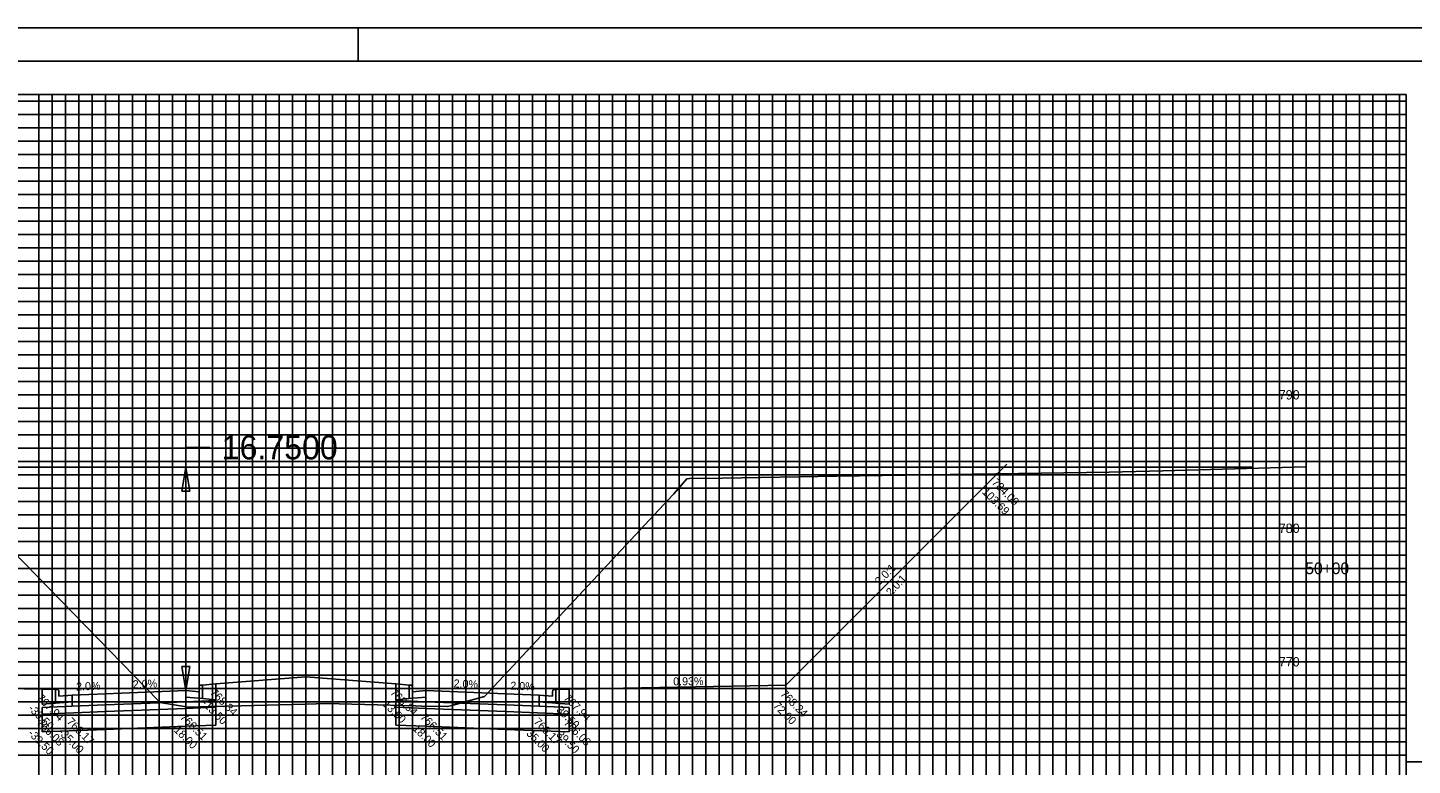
# Model space of a CAD drawing. Extents: x 578243 to 601557, y 174899 to 175559.
# Drawn here: x 600658.2 to 600865.7, y 175448.3 to 175558.8 of the extents above; entities that cross this region are included whole.
import ezdxf

# ---------------------------------------------------------------- set-up
doc = ezdxf.new("R2010")
doc.units = 0
for name, color, linetype in [('E_PROF_Grid', 7, 'Continuous'), ('E_PROF_GridMin', 7, 'Continuous'), ('P_CRDR_Label', 7, 'Continuous'), ('P_CRDR_Link', 7, 'Continuous'), ('P_E_XS_Ground', 7, 'Continuous'), ('P_RW_SlopeIntercepts', 7, 'Continuous'), ('P_XS_Text', 7, 'Continuous'), ('PLT_Sheet_Border', 7, 'Continuous'), ('PLT_Sheet_Info', 7, 'Continuous')]:
    doc.layers.add(name, color=color, linetype=linetype)

msp = doc.modelspace()

# ---------------------------------------------------------------- linework, layer by layer
at = {"layer": 'E_PROF_Grid'}
for p, q in [((600659.84, 175353.8), (600659.84, 175548.8)), ((600669.84, 175353.8), (600669.84, 175548.8)), ((600679.84, 175353.8), (600679.84, 175548.8)), ((600689.84, 175353.8), (600689.84, 175548.8)), ((600699.84, 175353.8), (600699.84, 175548.8)), ((600709.84, 175353.8), (600709.84, 175548.8)), ((600719.84, 175353.8), (600719.84, 175548.8)), ((600729.84, 175353.8), (600729.84, 175548.8)), ((600739.84, 175353.8), (600739.84, 175548.8)), ((600749.84, 175353.8), (600749.84, 175548.8)), ((600759.84, 175353.8), (600759.84, 175548.8)), ((600769.84, 175353.8), (600769.84, 175548.8)), ((600779.84, 175353.8), (600779.84, 175548.8)), ((600789.84, 175353.8), (600789.84, 175548.8)), ((600799.84, 175353.8), (600799.84, 175548.8)), ((600809.84, 175353.8), (600809.84, 175548.8)), ((600819.84, 175353.8), (600819.84, 175548.8)), ((600829.84, 175353.8), (600829.84, 175548.8)), ((600839.84, 175353.8), (600839.84, 175548.8)), ((600849.84, 175353.8), (600849.84, 175548.8)), ((600859.84, 175353.8), (600859.84, 175548.8)), ((600549.84, 175543.8), (600864.84, 175543.8)), ((600549.84, 175533.8), (600864.84, 175533.8)), ((600549.84, 175523.8), (600864.84, 175523.8)), ((600549.84, 175513.8), (600864.84, 175513.8)), ((600549.84, 175503.8), (600864.84, 175503.8)), ((600549.84, 175493.8), (600864.84, 175493.8)), ((600549.84, 175483.8), (600864.84, 175483.8)), ((600549.84, 175473.8), (600864.84, 175473.8)), ((600549.84, 175463.8), (600864.84, 175463.8)), ((600549.84, 175453.8), (600864.84, 175453.8))]:
    msp.add_line(p, q, dxfattribs=at)
at = {"layer": 'E_PROF_GridMin'}
for p, q in [((600661.84, 175353.8), (600661.84, 175548.8)), ((600663.84, 175353.8), (600663.84, 175548.8)), ((600665.84, 175353.8), (600665.84, 175548.8)), ((600667.84, 175353.8), (600667.84, 175548.8)), ((600671.84, 175353.8), (600671.84, 175548.8)), ((600673.84, 175353.8), (600673.84, 175548.8)), ((600675.84, 175353.8), (600675.84, 175548.8)), ((600677.84, 175353.8), (600677.84, 175548.8)), ((600681.84, 175353.8), (600681.84, 175548.8)), ((600683.84, 175353.8), (600683.84, 175548.8)), ((600685.84, 175353.8), (600685.84, 175548.8)), ((600687.84, 175353.8), (600687.84, 175548.8)), ((600691.84, 175353.8), (600691.84, 175548.8)), ((600693.84, 175353.8), (600693.84, 175548.8)), ((600695.84, 175353.8), (600695.84, 175548.8)), ((600697.84, 175353.8), (600697.84, 175548.8)), ((600701.84, 175353.8), (600701.84, 175548.8)), ((600703.84, 175353.8), (600703.84, 175548.8)), ((600705.84, 175353.8), (600705.84, 175548.8)), ((600707.84, 175353.8), (600707.84, 175548.8)), ((600711.84, 175353.8), (600711.84, 175548.8)), ((600713.84, 175353.8), (600713.84, 175548.8)), ((600715.84, 175353.8), (600715.84, 175548.8)), ((600717.84, 175353.8), (600717.84, 175548.8)), ((600721.84, 175353.8), (600721.84, 175548.8)), ((600723.84, 175353.8), (600723.84, 175548.8)), ((600725.84, 175353.8), (600725.84, 175548.8)), ((600727.84, 175353.8), (600727.84, 175548.8)), ((600731.84, 175353.8), (600731.84, 175548.8)), ((600733.84, 175353.8), (600733.84, 175548.8)), ((600735.84, 175353.8), (600735.84, 175548.8)), ((600737.84, 175353.8), (600737.84, 175548.8)), ((600741.84, 175353.8), (600741.84, 175548.8)), ((600743.84, 175353.8), (600743.84, 175548.8)), ((600745.84, 175353.8), (600745.84, 175548.8)), ((600747.84, 175353.8), (600747.84, 175548.8)), ((600751.84, 175353.8), (600751.84, 175548.8)), ((600753.84, 175353.8), (600753.84, 175548.8)), ((600755.84, 175353.8), (600755.84, 175548.8)), ((600757.84, 175353.8), (600757.84, 175548.8)), ((600761.84, 175353.8), (600761.84, 175548.8)), ((600763.84, 175353.8), (600763.84, 175548.8)), ((600765.84, 175353.8), (600765.84, 175548.8)), ((600767.84, 175353.8), (600767.84, 175548.8)), ((600771.84, 175353.8), (600771.84, 175548.8)), ((600773.84, 175353.8), (600773.84, 175548.8)), ((600775.84, 175353.8), (600775.84, 175548.8)), ((600777.84, 175353.8), (600777.84, 175548.8)), ((600781.84, 175353.8), (600781.84, 175548.8)), ((600783.84, 175353.8), (600783.84, 175548.8)), ((600785.84, 175353.8), (600785.84, 175548.8)), ((600787.84, 175353.8), (600787.84, 175548.8)), ((600791.84, 175353.8), (600791.84, 175548.8)), ((600793.84, 175353.8), (600793.84, 175548.8)), ((600795.84, 175353.8), (600795.84, 175548.8)), ((600797.84, 175353.8), (600797.84, 175548.8)), ((600801.84, 175353.8), (600801.84, 175548.8)), ((600803.84, 175353.8), (600803.84, 175548.8)), ((600805.84, 175353.8), (600805.84, 175548.8)), ((600807.84, 175353.8), (600807.84, 175548.8)), ((600811.84, 175353.8), (600811.84, 175548.8)), ((600813.84, 175353.8), (600813.84, 175548.8)), ((600815.84, 175353.8), (600815.84, 175548.8)), ((600817.84, 175353.8), (600817.84, 175548.8)), ((600821.84, 175353.8), (600821.84, 175548.8)), ((600823.84, 175353.8), (600823.84, 175548.8)), ((600825.84, 175353.8), (600825.84, 175548.8)), ((600827.84, 175353.8), (600827.84, 175548.8)), ((600831.84, 175353.8), (600831.84, 175548.8)), ((600833.84, 175353.8), (600833.84, 175548.8)), ((600835.84, 175353.8), (600835.84, 175548.8)), ((600837.84, 175353.8), (600837.84, 175548.8)), ((600841.84, 175353.8), (600841.84, 175548.8)), ((600843.84, 175353.8), (600843.84, 175548.8)), ((600845.84, 175353.8), (600845.84, 175548.8)), ((600847.84, 175353.8), (600847.84, 175548.8)), ((600851.84, 175353.8), (600851.84, 175548.8)), ((600853.84, 175353.8), (600853.84, 175548.8)), ((600855.84, 175353.8), (600855.84, 175548.8)), ((600857.84, 175353.8), (600857.84, 175548.8)), ((600861.84, 175353.8), (600861.84, 175548.8)), ((600863.84, 175353.8), (600863.84, 175548.8)), ((600549.84, 175547.8), (600864.84, 175547.8)), ((600549.84, 175545.8), (600864.84, 175545.8)), ((600549.84, 175541.8), (600864.84, 175541.8)), ((600549.84, 175539.8), (600864.84, 175539.8)), ((600549.84, 175537.8), (600864.84, 175537.8)), ((600549.84, 175535.8), (600864.84, 175535.8)), ((600549.84, 175531.8), (600864.84, 175531.8)), ((600549.84, 175529.8), (600864.84, 175529.8)), ((600549.84, 175527.8), (600864.84, 175527.8)), ((600549.84, 175525.8), (600864.84, 175525.8)), ((600549.84, 175521.8), (600864.84, 175521.8)), ((600549.84, 175519.8), (600864.84, 175519.8)), ((600549.84, 175517.8), (600864.84, 175517.8)), ((600549.84, 175515.8), (600864.84, 175515.8)), ((600549.84, 175511.8), (600864.84, 175511.8)), ((600549.84, 175509.8), (600864.84, 175509.8)), ((600549.84, 175507.8), (600864.84, 175507.8)), ((600549.84, 175505.8), (600864.84, 175505.8)), ((600549.84, 175501.8), (600864.84, 175501.8)), ((600549.84, 175499.8), (600864.84, 175499.8)), ((600549.84, 175497.8), (600864.84, 175497.8)), ((600549.84, 175495.8), (600864.84, 175495.8)), ((600549.84, 175491.8), (600864.84, 175491.8)), ((600549.84, 175489.8), (600864.84, 175489.8)), ((600549.84, 175487.8), (600864.84, 175487.8)), ((600549.84, 175485.8), (600864.84, 175485.8)), ((600549.84, 175481.8), (600864.84, 175481.8)), ((600549.84, 175479.8), (600864.84, 175479.8)), ((600549.84, 175477.8), (600864.84, 175477.8)), ((600549.84, 175475.8), (600864.84, 175475.8)), ((600549.84, 175471.8), (600864.84, 175471.8)), ((600549.84, 175469.8), (600864.84, 175469.8)), ((600549.84, 175467.8), (600864.84, 175467.8)), ((600549.84, 175465.8), (600864.84, 175465.8)), ((600549.84, 175461.8), (600864.84, 175461.8)), ((600549.84, 175459.8), (600864.84, 175459.8)), ((600549.84, 175457.8), (600864.84, 175457.8)), ((600549.84, 175455.8), (600864.84, 175455.8)), ((600549.84, 175451.8), (600864.84, 175451.8)), ((600549.84, 175449.8), (600864.84, 175449.8))]:
    msp.add_line(p, q, dxfattribs=at)
at = {"layer": 'P_CRDR_Link'}
msp.add_line((600804.95, 175493.4), (600771.84, 175460.28), dxfattribs=at)
for points in [[(600771.84, 175460.28), (600803.52, 175491.97)], [(600771.84, 175460.28), (600803.52, 175491.97)], [(600686.34, 175460.48), (600699.84, 175461.56)], [(600686.34, 175460.48), (600699.84, 175461.56)], [(600699.84, 175461.56), (600686.34, 175460.48)], [(600699.84, 175461.56), (600713.34, 175460.48)], [(600699.84, 175461.56), (600713.34, 175460.48)], [(600713.34, 175460.48), (600699.84, 175461.56)], [(600660.34, 175459.68), (600627.84, 175460.28)], [(600660.34, 175459.68), (600627.84, 175460.28)], [(600662.34, 175459.64), (600660.34, 175459.68)], [(600660.34, 175459.68), (600660.34, 175457.44)], [(600660.34, 175459.68), (600660.34, 175457.44)], [(600660.34, 175459.68), (600660.34, 175457.44)], [(600662.66, 175459.64), (600662.34, 175459.64)], [(600662.66, 175459.64), (600662.34, 175459.64)], [(600662.34, 175459.64), (600662.34, 175457.6)], [(600662.34, 175457.6), (600662.34, 175459.64)], [(600662.74, 175459.6), (600662.66, 175459.64)], [(600662.74, 175459.6), (600662.66, 175459.64)], [(600662.8, 175459.48), (600662.74, 175459.6)], [(600662.8, 175459.48), (600662.74, 175459.6)], [(600662.82, 175459.32), (600662.8, 175459.48)], [(600662.82, 175459.32), (600662.8, 175459.48)], [(600662.84, 175458.64), (600662.82, 175459.32)], [(600662.84, 175458.64), (600662.82, 175459.32)], [(600669.84, 175459), (600664.84, 175458.8)], [(600681.84, 175459.48), (600669.84, 175459)], [(600669.84, 175459), (600669.84, 175457.34)], [(600669.84, 175459), (600669.84, 175457.34)], [(600681.84, 175459.48), (600681.84, 175457.82)], [(600681.84, 175459.48), (600681.84, 175457.82)], [(600681.84, 175459.48), (600681.84, 175457.82)], [(600681.84, 175459.48), (600683.84, 175459.32)], [(600681.84, 175459.48), (600683.84, 175459.32)], [(600681.84, 175458.48), (600681.84, 175459.48)], [(600683.84, 175459.32), (600683.85, 175460)], [(600683.84, 175459.32), (600683.85, 175460)], [(600683.85, 175460), (600683.88, 175460.16)], [(600683.85, 175460), (600683.88, 175460.16)], [(600683.88, 175460.16), (600683.94, 175460.28)], [(600683.88, 175460.16), (600683.94, 175460.28)], [(600683.94, 175460.28), (600684.02, 175460.32)], [(600683.94, 175460.28), (600684.02, 175460.32)], [(600684.02, 175460.32), (600684.34, 175460.32)], [(600684.02, 175460.32), (600684.34, 175460.32)], [(600684.34, 175460.32), (600686.34, 175460.48)], [(600684.34, 175460.32), (600684.34, 175458.28)], [(600684.34, 175458.28), (600684.34, 175460.32)], [(600686.34, 175460.48), (600686.34, 175458.12)], [(600686.34, 175460.48), (600686.34, 175458.12)], [(600686.34, 175460.48), (600686.34, 175458.12)], [(600686.34, 175460.48), (600686.34, 175460.48)], [(600686.34, 175460.48), (600686.34, 175460.48)], [(600686.34, 175460.48), (600686.34, 175460.48)], [(600715.34, 175460.32), (600713.34, 175460.48)], [(600713.34, 175460.48), (600713.34, 175458.12)], [(600713.34, 175460.48), (600713.34, 175458.12)], [(600713.34, 175460.48), (600713.34, 175458.12)], [(600713.34, 175460.48), (600713.34, 175460.48)], [(600713.34, 175460.48), (600713.34, 175460.48)], [(600713.34, 175460.48), (600713.34, 175460.48)], [(600715.66, 175460.32), (600715.34, 175460.32)], [(600715.66, 175460.32), (600715.34, 175460.32)], [(600715.34, 175460.32), (600715.34, 175458.28)], [(600715.34, 175458.28), (600715.34, 175460.32)], [(600715.74, 175460.28), (600715.66, 175460.32)], [(600715.74, 175460.28), (600715.66, 175460.32)], [(600715.8, 175460.16), (600715.74, 175460.28)], [(600715.8, 175460.16), (600715.74, 175460.28)], [(600715.82, 175460), (600715.8, 175460.16)], [(600715.82, 175460), (600715.8, 175460.16)], [(600715.84, 175459.32), (600715.82, 175460)], [(600715.84, 175459.32), (600715.82, 175460)], [(600717.84, 175459.48), (600715.84, 175459.32)], [(600717.84, 175459.48), (600715.84, 175459.32)], [(600717.84, 175459.48), (600729.84, 175459)], [(600717.84, 175459.48), (600717.84, 175457.82)], [(600717.84, 175459.48), (600717.84, 175457.82)], [(600717.84, 175459.48), (600717.84, 175457.82)], [(600717.84, 175458.48), (600717.84, 175459.48)], [(600729.84, 175459), (600729.84, 175457.34)], [(600729.84, 175459), (600734.84, 175458.8)], [(600729.84, 175459), (600729.84, 175457.34)], [(600736.84, 175458.64), (600736.85, 175459.32)], [(600736.84, 175458.64), (600736.85, 175459.32)], [(600736.85, 175459.32), (600736.88, 175459.48)], [(600736.85, 175459.32), (600736.88, 175459.48)], [(600736.88, 175459.48), (600736.94, 175459.6)], [(600736.88, 175459.48), (600736.94, 175459.6)], [(600736.94, 175459.6), (600737.02, 175459.64)], [(600736.94, 175459.6), (600737.02, 175459.64)], [(600737.02, 175459.64), (600737.34, 175459.64)], [(600737.02, 175459.64), (600737.34, 175459.64)], [(600737.34, 175459.64), (600739.34, 175459.68)], [(600737.34, 175459.64), (600737.34, 175457.6)], [(600737.34, 175457.6), (600737.34, 175459.64)], [(600739.34, 175459.68), (600771.84, 175460.28)], [(600739.34, 175459.68), (600771.84, 175460.28)], [(600739.34, 175459.68), (600739.34, 175457.44)], [(600739.34, 175459.68), (600739.34, 175457.44)], [(600739.34, 175459.68), (600739.34, 175457.44)], [(600660.34, 175457.44), (600662.34, 175457.6)], [(600664.84, 175457.14), (600660.34, 175456.96)], [(600660.34, 175456.96), (600660.34, 175455.96)], [(600662.34, 175457.6), (600664.84, 175457.8)], [(600662.34, 175457.6), (600664.84, 175457.8)], [(600664.84, 175458.8), (600662.84, 175458.64)], [(600664.84, 175458.8), (600662.84, 175458.64)], [(600664.84, 175458.8), (600664.84, 175457.14)], [(600664.84, 175457.8), (600664.84, 175458.8)], [(600669.84, 175457.34), (600664.84, 175457.14)], [(600681.84, 175457.82), (600669.84, 175457.34)], [(600669.84, 175457.34), (600669.84, 175456.34)], [(600669.84, 175457.34), (600669.84, 175456.34)], [(600684.34, 175458.28), (600681.84, 175458.48)], [(600684.34, 175458.28), (600681.84, 175458.48)], [(600686.34, 175458), (600681.84, 175457.82)], [(600681.84, 175457.82), (600681.84, 175456.82)], [(600681.84, 175457.82), (600681.84, 175456.82)], [(600681.84, 175457.82), (600681.84, 175456.82)], [(600686.34, 175457), (600681.84, 175456.82)], [(600686.34, 175458.12), (600684.34, 175458.28)], [(600686.34, 175458), (600686.34, 175457)], [(600686.34, 175457), (600686.34, 175454.33)], [(600713.34, 175458.12), (600715.34, 175458.28)], [(600713.34, 175458), (600717.84, 175457.82)], [(600713.34, 175458), (600713.34, 175457)], [(600713.34, 175457), (600717.84, 175456.82)], [(600713.34, 175457), (600713.34, 175454.33)], [(600715.34, 175458.28), (600717.84, 175458.48)], [(600715.34, 175458.28), (600717.84, 175458.48)], [(600717.84, 175457.82), (600729.84, 175457.34)], [(600717.84, 175457.82), (600717.84, 175456.82)], [(600717.84, 175457.82), (600717.84, 175456.82)], [(600717.84, 175457.82), (600717.84, 175456.82)], [(600729.84, 175457.34), (600729.84, 175456.34)], [(600729.84, 175457.34), (600734.84, 175457.14)], [(600729.84, 175457.34), (600729.84, 175456.34)], [(600734.84, 175458.8), (600734.84, 175457.14)], [(600734.84, 175458.8), (600736.84, 175458.64)], [(600734.84, 175458.8), (600736.84, 175458.64)], [(600734.84, 175457.8), (600734.84, 175458.8)], [(600737.34, 175457.6), (600734.84, 175457.8)], [(600737.34, 175457.6), (600734.84, 175457.8)], [(600734.84, 175457.14), (600739.34, 175456.96)], [(600739.34, 175457.44), (600737.34, 175457.6)], [(600739.34, 175456.96), (600739.34, 175455.96)], [(600669.84, 175456.34), (600660.34, 175455.96)], [(600660.34, 175455.96), (600660.34, 175453.29)], [(600681.84, 175456.82), (600669.84, 175456.34)], [(600669.84, 175456.34), (600669.84, 175453.67)], [(600669.84, 175456.34), (600669.84, 175453.67)], [(600681.84, 175456.82), (600681.84, 175454.15)], [(600681.84, 175456.82), (600681.84, 175454.15)], [(600681.84, 175456.82), (600681.84, 175454.15)], [(600717.84, 175456.82), (600729.84, 175456.34)], [(600717.84, 175456.82), (600717.84, 175454.15)], [(600717.84, 175456.82), (600717.84, 175454.15)], [(600717.84, 175456.82), (600717.84, 175454.15)], [(600729.84, 175456.34), (600729.84, 175453.67)], [(600729.84, 175456.34), (600739.34, 175455.96)], [(600729.84, 175456.34), (600729.84, 175453.67)], [(600739.34, 175455.96), (600739.34, 175453.29)], [(600669.84, 175453.67), (600660.34, 175453.29)], [(600681.84, 175454.15), (600669.84, 175453.67)], [(600681.84, 175454.15), (600686.34, 175454.33)], [(600717.84, 175454.15), (600713.34, 175454.33)], [(600717.84, 175454.15), (600729.84, 175453.67)], [(600729.84, 175453.67), (600739.34, 175453.29)]]:
    msp.add_lwpolyline(points, dxfattribs=at)
at = {"layer": 'P_E_XS_Ground'}
msp.add_lwpolyline([(600652.24, 175484.1), (600677.78, 175457.95), (600677.97, 175457.69), (600681.94, 175457.07), (600682.75, 175457), (600685.31, 175457.08), (600685.85, 175457.09), (600690.17, 175457.22), (600699.84, 175457.45), (600702.96, 175457.53), (600712.52, 175457.32), (600716.31, 175457.21), (600717.24, 175457.16), (600721.11, 175457.09), (600721.72, 175457.24), (600726.66, 175458.6), (600754.94, 175488.85), (600755.03, 175488.94), (600756.99, 175491.23), (600756.99, 175491.23), (600757.38, 175491.24), (600762.33, 175491.32), (600779.46, 175491.61), (600820.3, 175492.22), (600828.35, 175492.41), (600849.84, 175493.01)], dxfattribs=at)
at = {"layer": 'P_RW_SlopeIntercepts'}
for p, q in [((600681.84, 175495.91), (600685.44, 175495.91)), ((600681.84, 175459.48), (600681.84, 175495.91)), ((600581.84, 175492.98), (600841.84, 175492.98))]:
    msp.add_line(p, q, dxfattribs=at)
for points in [[(600681.24, 175489.38), (600682.44, 175489.38), (600681.84, 175492.98)], [(600681.24, 175463.08), (600682.44, 175463.08), (600681.84, 175459.48)]]:
    msp.add_lwpolyline(points, close=True, dxfattribs=at)
at = {"layer": 'PLT_Sheet_Border'}
for points in [[(600537.19, 175338.8), (600877.19, 175338.8), (600877.19, 175558.8), (600537.19, 175558.8)], [(600539.59, 175343.8), (600870.59, 175343.8), (600870.59, 175553.8), (600539.59, 175553.8)]]:
    msp.add_lwpolyline(points, close=True, dxfattribs=at)
at = {"layer": 'PLT_Sheet_Info'}
for p, q in [((600702.69, 175558.8), (600712.69, 175558.8)), ((600707.69, 175558.8), (600707.69, 175553.8)), ((600549.84, 175548.8), (600864.84, 175548.8)), ((600864.84, 175348.8), (600864.84, 175548.8)), ((600877.19, 175448.8), (600864.84, 175448.8))]:
    msp.add_line(p, q, dxfattribs=at)

# ---------------------------------------------------------------- texts
at = {"layer": 'P_CRDR_Label'}
for s, rotation, p in [('784.09', 315, (600802.6, 175490.56)), ('784.09', 315, (600802.6, 175490.56)), ('103.69', 315, (600801.15, 175489.16)), ('103.69', 315, (600801.15, 175489.16)), ('2.0:1', 45, (600785.87, 175475.22)), ('2.0:1', 46.711, (600787.58, 175473.57)), ('2.0%', 2.2906, (600673.93, 175459.82)), ('2.0%', 357.7094, (600721.99, 175459.97)), ('0.93%', 0.4313, (600754.93, 175460.27)), ('767.94', 315, (600659.41, 175458.27)), ('2.0%', 2.2906, (600665.43, 175459.48)), ('768.34', 315, (600685.41, 175459.07)), ('768.34', 315, (600712.41, 175459.07)), ('2.0%', 357.7094, (600730.49, 175459.63)), ('767.94', 315, (600738.41, 175458.27)), ('768.24', 315, (600770.91, 175458.87)), ('-39.50', 315, (600658.14, 175456.7)), ('-13.50', 315, (600684.14, 175457.5)), ('13.50', 315, (600711.31, 175457.33)), ('39.50', 315, (600737.33, 175456.5)), ('72.00', 315, (600769.83, 175457.11)), ('766.08', 315, (600659.41, 175454.54)), ('766.17', 315, (600663.91, 175454.72)), ('766.51', 315, (600680.91, 175455.4)), ('766.51', 315, (600680.91, 175455.4)), ('766.51', 315, (600680.91, 175455.4)), ('766.51', 315, (600716.91, 175455.4)), ('766.51', 315, (600716.91, 175455.4)), ('766.51', 315, (600716.91, 175455.4)), ('766.17', 315, (600733.91, 175454.72)), ('766.08', 315, (600738.41, 175454.54)), ('-39.50', 315, (600658.13, 175452.98)), ('-35.00', 315, (600662.63, 175453.16)), ('-18.00', 315, (600679.62, 175453.85)), ('-18.00', 315, (600679.62, 175453.85)), ('-18.00', 315, (600679.62, 175453.85)), ('18.00', 315, (600715.79, 175453.68)), ('18.00', 315, (600715.79, 175453.68)), ('18.00', 315, (600715.79, 175453.68)), ('35.00', 315, (600732.82, 175452.97)), ('39.50', 315, (600737.32, 175452.79))]:
    msp.add_text(s, height=1.2, rotation=rotation, dxfattribs=at).set_placement(p)
at = {"layer": 'P_RW_SlopeIntercepts'}
msp.add_text('16.7500', height=3.6, dxfattribs=at).set_placement((600687.24, 175494.13))
at = {"layer": 'P_XS_Text'}
for s, height, p in [('790', 1.4, (600845.72, 175503.1)), ('780', 1.4, (600845.72, 175483.1)), ('50+00', 1.75, (600849.7, 175476.93)), ('770', 1.4, (600845.72, 175463.1))]:
    msp.add_text(s, height=height, rotation=360, dxfattribs=at).set_placement(p)

doc.saveas('drawing.dxf')
